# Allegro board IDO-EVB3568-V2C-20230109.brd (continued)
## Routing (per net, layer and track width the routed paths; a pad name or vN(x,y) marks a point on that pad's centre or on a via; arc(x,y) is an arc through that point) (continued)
SDMMC0_CMD: length 97.8
  TOP w0.127: J2.204 33.42,52.45 33.99,51.89 34.11,51.89 34.87,51.13 35.31,51.13 37.62,48.82 40.87,48.82 v1(41.1,48.59) ; R20.1 100.99,69.58 100.99,68.28 101.14,68.12 101.68,68.12 101.8,68 101.8,67.36 101.6,67.16 100.74,67.16 100.38,67.51 v1(100.38,68.86)
  BOTTOM w0.127: v1(41.1,48.59) 41.1,48.46 41.91,47.65 43.41,47.65 43.87,47.19 49.53,47.19 51.38,49.05 54.23,49.05 56.26,47.02 63.88,47.02 64.34,47.47 64.34,63.98 68.17,67.82 68.78,67.82 69.01,68.05 69.6,68.05 70.08,68.53 83.39,68.53 85.17,66.75 93.55,66.75 94.59,67.79 96.57,67.79 97.31,68.53 99.72,68.53 100.05,68.86 v1(100.38,68.86)
SDMMC0_CMD_: length 6.8
  TOP w0.127: J3.3 104,74.79 102.57,73.36 101.68,73.36 101.51,73.19 D3.6 D3.5 101.51,71.66 101.07,71.22 R20.2
SDMMC0_D0: length 97.1
  TOP w0.127: v1(42.67,49.61) 42.44,49.83 38.13,49.83 35.8,52.16 35.65,52.16 35.42,52.38 J2.196 ; R22.1 106.3,69.6 v1(105.49,69.6)
  BOTTOM w0.127: v1(42.67,49.61) 43.61,48.67 43.83,48.67 44.29,48.21 49.11,48.21 50.96,50.06 54.65,50.06 56.69,48.03 63.12,48.03 63.32,48.23 63.32,56.08 62.13,57.28 62.13,61.75 62.43,62.05 62.74,62.05 62.86,62.17 62.87,62.17 63.14,62.44 63.14,62.45 63.32,62.64 63.32,63.56 63.32,63.56 63.32,64.47 63.32,64.49 67.67,68.83 68.28,68.83 68.57,69.13 69.15,69.13 69.57,69.55 83.9,69.55 85.67,67.77 93.04,67.77 94.08,68.81 96.04,68.81 97.26,70.03 100.3,70.03 101.37,68.96 104.75,68.96 105.39,69.6 v1(105.49,69.6)
SDMMC0_D0_: length 6.9
  TOP w0.127: J3.7 108.41,75.56 108.41,74.5 108.1,74.19 106.83,74.19 106.51,73.87 D4.9 D4.2 106.51,71.59 106.76,71.35 106.76,70.91 R22.2
SDMMC0_D1: length 98.8
  TOP w0.127: v1(105.46,68.91) 105.87,68.91 105.99,69.04 106.72,69.04 R23.1 ; v1(42.04,49.35) 42.04,49.38 41.83,49.58 38,49.58 35.69,51.89 35.39,51.89 34.92,52.36 J2.198
  BOTTOM w0.127: v1(105.46,68.91) 105.11,68.91 104.9,68.71 101.24,68.71 100.18,69.77 97.38,69.77 96.16,68.55 94.21,68.55 93.17,67.51 85.55,67.51 83.77,69.29 69.7,69.29 69.27,68.86 68.68,68.86 68.4,68.58 67.81,68.58 63.58,64.34 63.58,63.67 63.58,62.36 63.02,61.8 62.76,61.8 62.41,61.44 62.41,57.38 63.58,56.21 63.58,47.96 63.4,47.78 56.58,47.78 54.55,49.81 51.07,49.81 49.21,47.96 44.19,47.96 43.73,48.41 43.43,48.41 42.75,49.1 42.29,49.1 v1(42.04,49.35)
SDMMC0_D1_: length 6.9
  TOP w0.127: J3.8 109.5,74.03 109.34,73.86 109.17,73.86 108.92,74.12 108.66,74.12 108.15,73.61 107.9,73.61 107.51,73.22 D4.7 D4.4 107.51,70.72 R23.2
SDMMC0_D2: length 98
  TOP w0.127: v1(42.49,48.59) 42.23,48.86 41.87,48.86 41.4,49.33 37.87,49.33 35.56,51.64 35.15,51.64 34.42,52.37 J2.200 ; v1(99.21,69.09) 99.21,69.55 R18.1
  BOTTOM w0.127: v1(42.49,48.59) 42.93,48.16 43.62,48.16 44.08,47.7 49.32,47.7 51.17,49.56 54.44,49.56 56.48,47.52 63.55,47.52 63.83,47.8 63.83,56.85 63.7,56.97 63.2,56.97 63.07,57.1 63.07,57.35 63.2,57.48 63.7,57.48 63.83,57.61 63.83,57.86 63.7,57.99 62.84,57.99 62.69,58.14 62.69,58.34 62.81,58.47 63.68,58.47 63.83,58.62 63.83,58.88 63.7,59 62.81,59 62.69,59.13 62.69,59.39 62.81,59.51 63.7,59.51 63.83,59.64 63.83,59.89 63.7,60.02 63.17,60.02 63.01,60.18 63.01,60.36 63.17,60.53 63.7,60.53 63.83,60.66 63.83,60.91 63.7,61.04 63.2,61.04 63.03,61.2 63.03,61.38 63.2,61.54 63.7,61.54 63.83,61.67 63.83,63.77 63.83,63.77 63.83,64.19 63.83,64.24 67.92,68.33 68.53,68.33 68.8,68.59 69.38,68.59 69.82,69.04 83.64,69.04 85.42,67.26 93.29,67.26 94.34,68.3 96.29,68.3 97.51,69.52 98.91,69.52 99.21,69.22 v1(99.21,69.09)
SDMMC0_D2_: length 6.8
  TOP w0.127: J3.1 101.8,74.78 101.27,74.24 100.41,74.24 100.01,73.85 D3.9 D3.2 100.01,71.66 99.54,71.2 99.19,71.2 99.11,71.11 R18.2
SDMMC0_D3: length 95.4
  TOP w0.127: J2.202 33.92,52.46 35,51.38 35.43,51.38 37.74,49.07 41.27,49.07 41.61,48.74 41.61,48.62 v1(41.83,48.39) ; R19.1 99.77,69.3 99.77,69.16 99.92,69.02 99.92,68.67 99.97,68.61 99.97,68.3 99.73,68.06 99.73,67.88 100,67.61 100,67.18 99.85,67.03 99.26,67.03 99.09,67.21 99.09,68.53 98.58,69.04 v1(98.48,69.04)
  BOTTOM w0.127: v1(41.83,48.39) 42.32,47.9 43.52,47.9 43.97,47.45 49.42,47.45 51.28,49.3 54.34,49.3 56.37,47.27 63.75,47.27 64.08,47.6 64.08,63.88 64.08,64.09 68.07,68.07 68.66,68.07 68.9,68.31 69.48,68.31 69.95,68.78 83.52,68.78 85.29,67.01 93.42,67.01 94.46,68.05 96.42,68.05 97.16,68.78 98.22,68.78 v1(98.48,69.04)
SDMMC0_D3_: length 6.8
  TOP w0.127: R19.2 100.13,71.11 100.34,71.32 100.74,71.32 101.01,71.59 D3.4 D3.7 101.01,73.32 101.55,73.86 102.21,73.86 102.9,74.56 J3.2
SDMMC0_DET_: length 6.9
  TOP w0.127: R24.2 108.01,70.62 D4.5 D4.6 108.01,73.09 108.15,73.23 109.3,73.23 110.6,74.54 J3.9
SDMMC0_DET_L: length 104.3
  TOP w0.127: R24.1 107.36,68.78 v1(107.26,68.78) ; v1(40.21,47.07) 39.7,47.07 38.96,47.8 37.11,47.8 35.51,49.4 34.26,49.4 33.81,49.86 32.56,49.86 32.36,50.06 32.36,52.3 32.42,52.36 J2.208
  BOTTOM w0.127: v1(40.21,47.07) 40.41,46.86 40.41,46.61 40.71,46.31 41.38,46.31 41.68,46.62 42.7,46.62 43.14,46.18 49.97,46.18 51.79,48.01 52.11,48.01 52.43,48.01 52.64,48.01 53.84,48.01 55.92,45.92 64.32,45.92 64.49,46.1 66.07,47.67 66.07,47.68 66.09,47.7 66.09,52.3 65.35,53.04 65.35,62.86 69.47,66.98 70.05,66.98 70.59,67.51 82.83,67.51 84.63,65.71 94.03,65.71 95.07,66.75 97.05,66.75 97.82,67.51 100.79,67.51 100.91,67.64 106.12,67.64 106.76,68.28 106.76,68.78 106.88,68.91 107.14,68.91 v1(107.26,68.78)
SDMMC2_CLK_M0: length 2.6
  TOP w0.127: J2.27 79.67,59.76 v1(79.45,59.54)
  BOTTOM w0.127: R187.1 79.45,59.07 v1(79.45,59.54)
SDMMC2_CMD_M0: length 57.2
  TOP w0.127: v1(95.83,45.09) 95.83,31.16 96.12,30.87 96.12,30.66 96.6,30.18 97.42,30.18 98.47,30.18 105.98,30.18 R185.2 107.7,27.5 R186.1 ; J2.25 80.2,61.43 80.2,60.34 80.24,60.3 v1(80.24,60.27)
  BOTTOM w0.127: v1(95.83,45.09) 95.83,45.11 95.15,45.8 94.01,45.8 93.9,45.69 93.48,45.69 85.63,45.69 82.25,49.08 82.25,52.65 82.37,52.78 82.5,52.78 82.63,52.91 82.63,53.16 82.5,53.29 82.37,53.29 82.25,53.42 82.25,57.73 82.12,57.86 81.86,57.86 80.24,59.49 v1(80.24,60.27)
SDMMC2_D0_M0: length 58.5
  TOP w0.127: R181.1 105.23,27.97 104.85,27.97 104.37,28.45 R180.2 103.64,29.13 96.4,29.13 96.21,29.13 95.11,30.24 95.11,30.45 94.69,30.87 94.69,43.56 94.54,43.71 94.03,44.23 94.03,46.74 v1(93.95,46.81) ; v1(82.3,60.15) 82.17,60.27 J2.17
  BOTTOM w0.127: v1(93.95,46.81) 93.57,47.19 85.67,47.19 83.26,49.61 83.26,51.89 84.4,53.04 84.4,56.08 84.28,56.21 83.39,56.21 83.26,56.34 83.26,56.59 83.39,56.72 84.28,56.72 84.4,56.85 84.4,57.1 84.28,57.23 83.39,57.23 83.26,57.35 83.26,57.61 83.39,57.73 84.28,57.73 84.4,57.86 84.4,58.12 84.28,58.24 83.39,58.24 83.26,58.37 83.26,58.62 83.39,58.75 83.39,59.06 v1(82.3,60.15)
SDMMC2_D1_M0: length 58.4
  TOP w0.127: R182.1 104.5,27.45 103.07,28.88 96.5,28.88 96.1,28.88 94.85,30.13 94.85,30.35 94.44,30.76 94.44,43.46 93.78,44.12 93.78,46.2 v1(93.27,46.71) ; v1(81.83,59.61) 81.83,60.31 81.67,60.47 J2.19
  BOTTOM w0.127: v1(93.27,46.71) 85.76,46.71 83.01,49.46 83.01,52.02 84.15,53.16 84.15,53.8 84.02,53.92 83.13,53.92 83.01,54.05 83.01,54.31 83.13,54.43 84.02,54.43 84.15,54.56 84.15,54.81 84.02,54.94 83.13,54.94 83.01,55.07 83.01,55.32 83.13,55.45 84.02,55.45 84.15,55.58 84.15,55.83 84.02,55.96 83.13,55.96 83.01,56.08 83.01,58.12 82.59,58.53 82.59,58.71 82.85,58.98 82.85,59.16 82.65,59.36 82.47,59.36 82.33,59.22 82.02,59.22 81.83,59.42 v1(81.83,59.61)
SDMMC2_D2_M0: length 59.2
  TOP w0.127: R183.1 109.6,28.98 107.9,30.68 96.81,30.68 96.63,30.87 96.63,31.08 96.37,31.35 96.37,43.84 96.85,44.33 96.85,45.44 v1(96.6,45.69) ; J2.21 81.17,60.3 v1(81.33,60.15)
  BOTTOM w0.127: v1(96.6,45.69) 95.76,46.53 94.33,46.53 94.15,46.35 93.84,46.35 93.69,46.2 85.88,46.2 82.75,49.33 82.75,52.15 83.13,52.53 83.13,53.54 82.75,53.92 82.75,57.99 81.33,59.42 v1(81.33,60.15)
SDMMC2_D3_M0: length 59.2
  TOP w0.127: R184.1 108.66,28.02 109.04,28.4 109.04,29.16 107.77,30.43 98.36,30.43 98.36,30.43 98.15,30.43 96.71,30.43 96.38,30.76 96.38,30.98 96.11,31.24 96.11,43.97 96.6,44.45 96.6,45.03 v1(95.86,45.77) ; J2.23 80.67,60.45 80.81,60.31 v1(80.81,59.66)
  BOTTOM w0.127: v1(80.81,59.66) 80.81,59.55 82.5,57.86 82.5,53.8 82.88,53.42 82.88,52.65 82.5,52.27 82.5,49.21 85.76,45.95 93.59,45.95 93.8,45.95 93.94,46.09 94.25,46.09 94.44,46.28 95.35,46.28 v1(95.86,45.77)
SPI0_CLK: length 6.6
  TOP w0.127: J24.3 129.87,53.67 129.87,51.77 128.6,50.5 128.19,50.5 127.81,50.88 R315.6
SPI0_CLK_M1: length 82.3
  TOP w0.127: R315.3 125.94,50.88 v1(125.93,50.88) ; v1(67.8,62.8) 67.73,62.74 66.57,62.74 66.17,62.34 J2.81
  BOTTOM w0.127: v1(125.93,50.88) 126.19,51.13 126.19,52.91 123.77,55.32 123.77,57.35 121.36,59.77 121.36,63.96 121.08,64.24 121.08,68.02 118.54,70.56 113.41,70.56 112.52,69.67 110.44,69.67 107.14,66.37 102.82,66.37 101.93,65.48 95.68,65.48 94.18,63.98 88.34,63.98 87.88,64.44 84,64.44 82.19,66.24 71.2,66.24 69.42,64.47 68.88,64.47 67.8,63.38 v1(67.8,62.8)
SPI0_CS0: length 10.1
  TOP w0.127: R315.5 127.45,50 127.97,49.48 129.11,49.48 130.63,51 131.78,51 132.16,51.38 132.16,53.42 J24.4
SPI0_CS0_M1: length 82.1
  TOP w0.127: R315.4 125.77,50.33 v1(125.3,49.86) ; J2.83 65.67,62.37 66.29,62.99 67.31,62.99 68,63.68 71.28,63.68 71.28,63.69 71.31,63.69 74.12,66.5 77.8,66.5 78.54,65.76 80.11,65.76 v1(80.37,65.51)
  BOTTOM w0.127: v1(80.37,65.51) 80.85,65.02 82.27,65.02 83.48,63.82 83.48,62.98 84,62.46 94.95,62.46 96.44,63.96 102.72,63.96 103.61,64.85 109.42,64.85 112.22,67.64 116.79,67.64 117.3,67.13 117.93,67.13 118.44,66.62 118.44,59.41 118.97,58.88 120.73,58.88 122.76,56.85 122.76,54.81 124.66,52.91 124.66,50.5 v1(125.3,49.86)
SPI0_MISO: length 10.1
  TOP w0.127: J24.2 133.55,57.23 132.54,56.21 130.51,56.21 129.31,55.02 129.31,52.6 128.22,51.51 127.83,51.51 127.7,51.38 R315.7
SPI0_MISO_M1: length 82.7
  TOP w0.127: J2.87 64.67,62.29 65.89,63.5 67.1,63.5 67.79,64.19 71.05,64.19 71.53,64.66 73.87,67.01 78.05,67.01 78.79,66.27 85.34,66.27 87.45,64.16 v1(87.45,63.7) ; R315.2 125.48,51.38 125.2,51.66 v1(125.2,51.69)
  BOTTOM w0.127: v1(125.2,51.69) 125.68,52.17 125.68,52.65 123.27,55.07 123.27,57.1 120.8,59.56 119.41,59.56 118.95,60.02 118.95,67.39 117.93,68.4 112.85,68.4 112.22,69.04 110.57,69.04 107.39,65.86 103.07,65.86 102.18,64.97 95.94,64.97 94.44,63.47 87.68,63.47 v1(87.45,63.7)
SPI0_MOSI: length 7.5
  TOP w0.127: J24.1 131.01,57.1 129.06,55.14 129.06,52.73 128.09,51.77 127.84,51.77 127.67,51.93 R315.8
SPI0_MOSI_M1: length 80.3
  TOP w0.127: J2.85 65.17,62.3 66.12,63.25 67.2,63.25 67.89,63.93 71.17,63.93 73.99,66.75 77.93,66.75 78.66,66.01 80.54,66.01 v1(81.05,65.51) ; v1(125.2,52.4) 125.67,51.93 R315.1
  BOTTOM w0.127: v1(125.2,52.4) 125.2,52.76 123.01,54.94 123.01,56.97 120.78,59.21 119.35,59.21 118.69,59.87 118.69,66.75 118.02,67.42 117.39,67.42 116.92,67.89 112.11,67.89 109.32,65.1 103.48,65.1 102.59,64.21 96.32,64.21 94.82,62.71 84.23,62.71 83.74,63.2 83.74,63.93 82.4,65.28 81.28,65.28 v1(81.05,65.51)
SPK_CTL_H_GPIO3_B0: length 12.4
  TOP w0.127: R89.1 81.1,63.58 v1(81.1,63.02) ; J2.53 73.17,60.35 v1(72.97,60.15)
  BOTTOM w0.127: v1(72.97,60.15) 72.97,60.66 75.34,63.02 75.64,63.02 75.84,63.22 78.89,63.22 79.15,63.47 80.98,63.47 81.1,63.35 v1(81.1,63.02)
SPK_MUTE_H_GPIO3_A7: length 13.2
  TOP w0.127: R90.1 83.2,63.2 v1(82.17,63.2) ; v1(74.14,62.99) 73.71,62.56 72.97,62.56 72.67,62.26 J2.55
  BOTTOM w0.127: v1(74.14,62.99) 74.17,62.99 74.73,63.55 75.41,63.55 75.59,63.73 78.64,63.73 78.89,63.98 81.33,63.98 82.12,63.2 v1(82.17,63.2)
SYS_LED_GPIO4_C5: length 56.3
  TOP w0.127: R8.1 76.53,76.66 76.78,76.4 76.78,73.28 76.66,73.15 75.93,73.15 75.72,73.15 75.18,72.62 75.18,71.41 75.46,71.13 75.46,70.18 v1(75.51,70.13) ; v1(51.49,51.13) 51.49,51.19 51.51,51.21 51.51,51.77 50.92,52.35 J2.142
  BOTTOM w0.127: v1(75.51,70.13) 75.46,70.18 74.68,70.18 73.96,70.89 72.62,70.89 71.86,70.13 70.79,70.13 70.41,70.51 70,70.51 68.88,69.39 68.45,69.39 68.15,69.09 67.49,69.09 61.44,63.04 61.44,57.2 62.79,55.85 62.79,49.12 61.95,48.29 56.79,48.29 54.76,50.32 52.07,50.32 51.51,50.88 51.51,51.05 51.49,51.07 v1(51.49,51.13)
SYS_RESETN: length 183.9
  TOP w0.127: R311.4 127.22,28.03 126.75,28.5 126.75,28.76 125.05,30.45 124.95,30.45 124.72,30.68 124.51,30.68 124.51,30.68 124.36,30.68 124.1,30.94 v1(123.77,30.94) ; v1(24.36,55.88) 24.43,55.96 24.97,55.96 26.37,57.35 26.37,59.94 25.67,60.64 J2.235
  BOTTOM w0.127: v1(24.36,55.88) 25.3,55.88 25.65,55.52 25.65,53.39 24.56,52.3 24.56,44.46 23.58,43.48 23.58,42.86 23.46,42.74 23.46,28.81 25.98,26.28 25.98,23.95 24.97,22.94 24.97,22.17 24.08,21.29 24.08,19.51 24.59,19 27.23,19 28.24,17.98 28.24,14.63 29.18,13.69 29.18,13.24 29.68,12.75 29.68,11.92 30.3,11.29 30.3,8.74 31.22,7.82 35.26,7.82 37.69,5.38 70.66,5.38 77.8,12.52 77.8,15.06 78.18,15.44 78.18,17.09 80.85,19.76 81.23,19.76 81.87,20.4 81.87,20.68 84.04,22.85 84.04,22.87 84.98,23.81 85,23.81 86.11,24.92 89.05,24.92 89.41,24.56 91.64,24.56 93.27,26.19 93.27,28.73 94.03,29.49 109.27,29.49 109.75,29.01 111.58,29.01 112.27,28.32 113.97,28.32 115.82,30.18 115.85,30.18 121.41,35.74 122.38,35.74 122.5,35.61 122.5,32.21 v1(123.77,30.94)
TP0_INT: length 49.2
  TOP w0.127: v1(31.83,10.64) 31.83,10.29 31.55,10.01 31.19,10.01 28.5,7.31 v1(28.5,6.78)
  BOTTOM w0.127: J15.5 18.08,27.51 17.6,27.03 17.6,20.14 19.51,18.24 20.65,18.24 22.3,16.59 22.3,13.67 24.33,11.63 25.6,11.63 27.51,9.73 27.51,7.06 27.79,6.78 v1(28.5,6.78) ; v1(31.83,10.64) 31.11,11.35 31.11,12.58 31.09,12.6 31.09,12.62 30.68,13.03 30.68,14.3 29.54,15.44 29.54,16.59 29.06,17.07 29.06,17.88 29.29,18.11 J31.3 29.29,20.02 29.67,20.4 31.55,20.4 31.71,20.56 D48.4 D48.7 31.71,22.95 R114.2
TP0_INT_L_GPIO3_A3: length 93.1
  TOP w0.127: v1(42.88,19.84) 42.01,20.7 39.63,20.7 39.45,20.88 v1(38.79,20.88) ; J2.63 70.67,62.25 70.21,62.71 70.2,62.71 v1(70.18,62.73)
  BOTTOM w0.127: v1(70.18,62.73) 70.18,62.64 68.58,61.04 67.89,61.04 67.64,60.78 67.64,46.94 65.1,44.4 55.22,44.4 53.14,46.48 52.43,46.48 52.02,46.08 52.02,45.24 48.59,41.81 48.59,37.29 49.23,36.65 49.23,27.51 50.24,26.49 50.24,22.68 49.15,21.59 47.09,21.59 45.82,20.32 45.82,19.96 45.26,19.41 43.28,19.41 42.93,19.76 42.93,19.79 v1(42.88,19.84) ; R114.1 31.88,26.54 32.18,26.85 32.58,26.85 32.79,26.85 34.26,28.31 37.8,28.31 38.22,28.31 38.77,27.76 38.77,26.38 38.51,26.12 38.51,21.16 v1(38.79,20.88)
TP0_RST: length 46.4
  TOP w0.127: v1(27.98,7.25) 28.08,7.25 31.17,10.34 v1(31.17,10.49)
  BOTTOM w0.127: J15.4 18.12,27.01 17.86,26.75 17.86,20.27 19.63,18.49 20.78,18.49 22.56,16.71 22.56,13.79 24.46,11.89 25.73,11.89 27.76,9.86 27.76,7.47 v1(27.98,7.25) ; R113.2 31.21,22.83 D48.6 D48.5 31.21,20.79 31.06,20.65 29.41,20.65 28.79,20.03 J31.2 28.79,16.96 29.29,16.46 29.29,15.32 30.43,14.17 30.43,12.9 30.86,12.47 30.86,11.23 31.17,10.92 v1(31.17,10.49)
TP0_RST_L_GPIO3_A4: length 94.8
  TOP w0.127: J2.61 71.17,62.46 70.41,63.22 69.7,63.22 v1(69.68,63.2)
  BOTTOM w0.127: R113.1 31.45,24.55 31.45,26.49 32.05,27.1 32.69,27.1 34.15,28.57 37.69,28.57 38.32,28.57 38.62,28.27 38.62,28.27 39.02,27.87 39.02,26.28 38.79,26.04 38.79,21.56 39.75,20.6 42.77,20.6 43.71,19.66 45.03,19.66 45.57,20.19 45.57,20.45 46.96,21.84 49.04,21.84 49.99,22.79 49.99,26.37 48.84,27.51 48.84,36.65 48.34,37.16 48.34,41.92 51.77,45.35 51.77,46.18 52.32,46.74 53.29,46.74 55.37,44.65 64.97,44.65 67.39,47.07 67.39,60.91 67.77,61.29 68.47,61.29 69.67,62.49 69.67,63.19 v1(69.68,63.2)
TP0_SCL: length 54.1
  TOP w0.127: v1(31.37,9.5) 31.05,9.5 29.03,7.49 29.03,7.47 28.98,7.42 28.98,6.55 28.73,6.3 v1(28.02,6.3)
  BOTTOM w0.127: R115.2 32.71,22.99 D48.9 D48.2 32.71,20.52 32.33,20.14 30.05,20.14 29.79,19.88 J31.4 29.79,18.11 30.02,17.88 30.02,15.34 30.94,14.43 30.94,13.16 32.33,11.76 32.33,9.88 31.95,9.5 v1(31.37,9.5) ; J15.6 17.08,28.01 16.59,27.51 16.59,25.25 17.35,24.49 17.35,20.02 18.49,18.87 18.49,14.17 20.02,12.65 22.94,12.65 24.21,11.38 25.48,11.38 27.25,9.6 27.25,6.81 27.76,6.3 v1(28.02,6.3)
TP0_SDA: length 56.1
  TOP w0.127: v1(29.16,6.05) 29.29,6.17 29.29,7.38 30.73,8.82 v1(31.34,8.82)
  BOTTOM w0.127: J15.7 17.22,28.51 16.33,27.62 16.33,25.1 17.09,24.33 17.09,19.89 18.24,18.75 18.24,14.07 19.91,12.4 22.81,12.4 24.08,11.13 25.35,11.13 27,9.47 27,6.43 27.64,5.79 28.91,5.79 v1(29.16,6.05) ; R116.2 33.66,23.12 33.21,22.67 D48.10 D48.1 33.21,20.53 32.56,19.89 30.57,19.89 30.29,19.61 J31.5 30.29,15.46 31.19,14.55 31.19,13.28 32.61,11.86 32.61,9.7 31.73,8.82 v1(31.34,8.82)
TP1_INT: length 5.8
  TOP w0.127: R95.2 92.91,13.46 D34.2 D34.9 92.91,10.86 92.66,10.62 92.15,10.62 91.04,9.5 J13.5
TP1_INT_L_GPIO3_C0: length 56.6
  TOP w0.127: J2.68 69.42,52.27 76.66,45.03 76.66,43.64 80.47,39.83 80.47,35 80.59,34.87 80.59,28.78 78.87,27.05 78.87,25.35 v1(79.98,24.23) ; R95.1 92.91,14.68 93.22,14.99 93.22,16.28 90.97,18.52 82.28,18.52 79.07,21.74 79.07,22.96 v1(78.84,23.19)
  BOTTOM w0.127: v1(79.98,24.23) 79.6,24.23 78.84,23.47 v1(78.84,23.19)
TP1_RST: length 5.9
  TOP w0.127: J13.4 91.54,9.5 92.41,10.36 92.91,10.36 93.41,10.86 D34.10 D34.1 93.41,12.56 93.65,12.81 93.65,13.31 R94.2
TP1_RST_L_GPIO3_C1: length 56.7
  TOP w0.127: v1(79.55,23.32) 79.32,23.09 79.32,21.84 82.39,18.78 91.08,18.78 91.09,18.77 91.11,18.77 93.55,16.33 93.55,14.94 93.8,14.68 R94.1 ; J2.66 69.92,52.15 76.91,45.16 76.91,43.76 80.72,39.95 80.72,35.13 80.85,35 80.85,28.65 79.12,26.92 79.12,25.6 80.01,24.71 80.47,24.71 v1(80.59,24.59)
  BOTTOM w0.127: v1(79.55,23.32) 79.76,23.32 80.59,24.16 v1(80.59,24.59)
TP1_SCL: length 5.3
  TOP w0.127: J13.6 90.54,9.51 91.9,10.87 91.9,11.19 D34.7 D34.4 91.91,13.35 R96.2
TP1_SDA: length 5.4
  TOP w0.127: J13.7 90.04,9.52 91.41,10.89 D34.6 D34.5 91.41,13.2 R97.2
TYPEC_CC1: length 43
  TOP w0.127: v1(115.7,67.16) 115.9,67.36 115.9,72.85 v1(116.13,73.08) ; J5.A5 129.22,82.2 D8.2 128.6,81.58 128.6,81.08 128.47,80.95 128.47,80.34 128.16,80.03 127.55,80.03 125.32,77.8 125.32,75.97 v1(124.38,75.03)
  BOTTOM w0.127: v1(115.7,67.16) 116.89,67.16 117.17,66.88 117.81,66.88 118.19,66.5 118.19,59.21 118.95,58.45 118.95,57.41 R38.1 118.19,56.65 D11.C ; v1(124.38,75.03) 124,75.03 123.65,75.39 115.95,75.39 115.29,74.73 115.29,73.91 v1(116.13,73.08)
TYPEC_CC2: length 37.9
  TOP w0.127: J5.B5 126.22,83.41 125.83,83.03 125.83,82.65 125.81,82.63 125.81,82.53 125.37,82.09 D9.2 124.97,82.09 124.84,81.96 124.84,81.05 124.39,80.59 123.95,80.59 122.71,79.35 122.71,76.33 123.39,75.64 123.39,73.74 122.94,73.28 121.06,73.28 120.73,73.61 117.81,73.61 117.64,73.44 117.64,72.22 117.14,71.73 117.14,67.54 117.32,67.36 117.32,66.62 v1(117.56,66.38)
  BOTTOM w0.127: v1(117.56,66.38) 117.93,66.01 117.93,60.22 115.9,58.19 115.9,57.39 R40.1 116.41,56.88 D13.C
UART0_CTSN: length 110.4
  TOP w0.127: J2.134 52.92,50.93 51.41,49.42 51.41,46.37 51.3,46.26 51.3,43.78 51.84,43.24 51.84,40.84 51.03,40.02 51.03,39.7 51.05,39.68 v1(51.05,39.67) ; R310.2 126.06,39.82 125.43,40.46 125.43,40.97 v1(124.79,41.61)
  BOTTOM w0.127: v1(124.79,41.61) 124.16,41.61 124,41.45 122.02,41.45 121.11,42.37 120.6,42.37 119.84,41.61 117.81,41.61 117.3,42.11 113.61,42.11 109.3,37.8 106.38,37.8 105.61,37.03 100.15,37.03 99.77,36.65 97.32,36.65 94.53,39.45 77.93,39.45 75.77,37.29 74.75,37.29 74.24,36.78 74.24,35.76 67.13,28.65 56.85,28.65 56.08,29.41 52.78,29.41 51.26,30.94 51.26,39.47 51.05,39.67 v1(51.05,39.67)
UART0_CTSN_: length 7
  TOP w0.127: J24.16 132.41,38.43 130.51,38.43 129.11,39.82 R310.7
UART0_RTSN: length 109.6
  TOP w0.127: J2.128 54.42,51.71 51.92,49.21 51.92,46.16 51.81,46.05 51.81,43.99 52.55,43.25 52.55,42.86 v1(52.56,42.85) ; R310.1 126.15,40.37 125.81,40.72 v1(125.81,41.38)
  BOTTOM w0.127: v1(125.81,41.38) 125.3,41.88 125.3,42.24 124.92,42.62 124.18,42.62 123.52,41.96 122.28,41.96 121.36,42.88 113.23,42.88 108.92,38.56 105.99,38.56 105.23,37.8 99.77,37.8 99.39,37.41 97.7,37.41 95.05,40.06 94.9,40.21 77.55,40.21 75.39,38.05 74.37,38.05 73.48,37.16 73.48,36.14 66.75,29.41 57.23,29.41 56.46,30.18 53.16,30.18 52.02,31.32 52.02,41.49 52.56,42.03 v1(52.56,42.85)
UART0_RTSN_: length 3.8
  TOP w0.127: R310.8 130.21,40.37 J24.15
UART0_RX: length 110.8
  TOP w0.127: v1(124.33,42.11) 124.97,42.75 125.93,42.75 126.18,42.5 R309.3 ; v1(52.78,44.53) 52.78,44.88 53.35,45.45 53.35,45.94 52.93,46.35 52.93,48.79 56.42,52.28 J2.120
  BOTTOM w0.127: v1(52.78,44.53) 52.22,44.53 51.51,43.81 51.51,31.06 52.91,29.67 56.21,29.67 56.97,28.91 67.01,28.91 73.99,35.89 73.99,36.91 74.63,37.54 75.64,37.54 77.8,39.7 94.69,39.7 97.49,36.91 99.64,36.91 100.03,37.29 105.49,37.29 106.25,38.05 109.17,38.05 113.49,42.37 117.42,42.37 117.93,41.86 119.71,41.86 120.47,42.62 121.23,42.62 122.15,41.71 123.72,41.71 124.13,42.11 v1(124.33,42.11)
UART0_RX_: length 6.7
  TOP w0.127: R309.6 129.75,42.5 130.4,43.15 132.51,43.15 J24.14
UART0_TX: length 108.2
  TOP w0.127: v1(52.78,45.54) 52.68,45.64 52.68,48.89 55.92,52.13 J2.122 ; v1(125.81,42.11) 125.97,41.95 R309.4
  BOTTOM w0.127: v1(125.81,42.11) 124.79,43.13 123.67,43.13 123.55,43.01 121.97,43.01 121.81,43.17 121.6,43.38 113,43.38 112.85,43.23 108.68,39.07 105.74,39.07 104.98,38.3 99.52,38.3 98.88,38.94 96.89,38.94 95.56,40.27 95.11,40.72 77.29,40.72 75.13,38.56 74.12,38.56 72.97,37.41 72.97,36.47 66.42,29.92 57.48,29.92 56.72,30.68 53.42,30.68 52.53,31.57 52.53,41.27 54.18,42.93 54.18,44.7 53.59,45.29 53.04,45.29 v1(52.78,45.54)
UART0_TX_: length 3.5
  TOP w0.127: R309.5 129.71,41.95 129.87,42.11 J24.13
UART2_RX_M0: length 12.8
  TOP w0.127: v1(56.59,63.32) 56.59,63.53 55.7,64.41 R25.1 ; J2.116 57.42,54.12 57.61,54.31 57.61,57.73 56.36,58.98 56.36,59.99 v1(56.26,60.1)
  BOTTOM w0.127: v1(56.26,60.1) 56.26,60.12 56.08,60.3 56.08,62.38 56.21,62.51 56.21,62.94 v1(56.59,63.32)
UART2_TX_M0: length 15.8
  TOP w0.127: v1(55.74,62.76) 52.58,62.76 52.15,63.2 R26.1 ; v1(55.75,59.61) 55.75,59.21 57.35,57.61 57.35,54.56 56.92,54.13 J2.118
  BOTTOM w0.127: v1(55.75,59.61) 55.58,59.79 55.58,62.6 v1(55.74,62.76)
UART4_RX: length 6.7
  TOP w0.127: R309.7 128.22,43 128.22,43 129.62,43 130.12,43.51 132.41,43.51 J24.12
UART4_RX_M1: length 70.9
  TOP w0.127: v1(125.68,43.51) 126.19,43 R309.2 ; J2.82 65.92,51.7 67.26,50.37 68.68,50.37 74.37,44.68 74.37,44.02 v1(74.88,43.51)
  BOTTOM w0.127: v1(74.88,43.51) 75.11,43.74 79.22,43.74 81.99,40.97 95.22,40.97 95.96,40.23 97,39.19 99.01,39.19 99.64,38.56 101.84,38.56 104.85,38.56 105.61,39.32 108.58,39.32 112.75,43.49 112.9,43.64 121.7,43.64 122.07,43.26 123.44,43.26 123.56,43.38 124.9,43.38 124.97,43.31 125.48,43.31 v1(125.68,43.51)
UART4_TX: length 4
  TOP w0.127: R309.8 127.93,43.55 128.09,43.38 129.49,43.38 130.76,44.65 J24.11
UART4_TX_M1: length 70.1
  TOP w0.127: v1(125.68,44.2) 126.33,43.55 R309.1 ; J2.80 66.42,51.59 67.39,50.62 68.79,50.62 74.63,44.78 74.63,44.5 v1(74.88,44.25)
  BOTTOM w0.127: v1(74.88,44.25) 75.13,43.99 79.35,43.99 82.12,41.22 95.33,41.22 97.1,39.45 99.14,39.45 99.77,38.81 101.94,38.81 101.94,38.81 104.72,38.81 105.49,39.57 108.47,39.57 112.49,43.59 112.79,43.89 121.6,43.89 121.6,43.89 121.81,43.89 122.18,43.52 123.34,43.52 123.46,43.64 125.12,43.64 v1(125.68,44.2)
UART5_RX: length 6.7
  TOP w0.127: R316.6 127.77,48.02 127.88,47.92 128.06,47.92 128.42,48.29 132.46,48.29 J24.10
UART5_RX_M1: length 67.4
  TOP w0.127: v1(76.3,47.41) 75.45,47.41 70.92,51.94 J2.62 ; R316.3 126,48.02 v1(125.68,47.7)
  BOTTOM w0.127: v1(125.68,47.7) 125.3,47.32 125.3,44.91 124.54,44.15 123.25,44.15 123.16,44.06 122.35,44.06 122.02,44.4 121.39,44.4 121.38,44.4 112.53,44.4 112.38,44.25 108.21,40.08 105.23,40.08 104.47,39.32 102.16,39.32 102.16,39.32 100.03,39.32 99.39,39.95 97.36,39.95 95.58,41.73 82.37,41.73 76.7,47.41 v1(76.3,47.41)
UART5_TX: length 4.1
  TOP w0.127: J24.9 130.18,48.03 128.55,48.03 128.17,47.65 127.91,47.65 127.74,47.47 R316.5
UART5_TX_M1: length 67.6
  TOP w0.127: v1(75.9,46.86) 75.62,46.86 70.42,52.06 J2.64 ; v1(125.81,46.79) 125.81,47.07 126.21,47.47 R316.4
  BOTTOM w0.127: v1(75.9,46.86) 76.86,46.86 82.25,41.48 95.45,41.48 97.23,39.7 99.26,39.7 99.9,39.07 102.05,39.07 104.6,39.07 105.36,39.83 108.32,39.83 112.64,44.15 121.49,44.15 121.91,44.15 122.28,43.77 123.23,43.77 123.35,43.89 124.66,43.89 125.55,44.78 125.55,46.53 v1(125.81,46.79)
UART7_RX: length 3.9
  TOP w0.127: R316.8 127.61,49.07 127.79,48.9 130.18,48.9 J24.7
UART7_RX_M1: length 67
  TOP w0.127: J2.58 71.92,51.7 75.23,48.39 v1(76.28,48.39) ; v1(125.04,48.51) 125.6,49.07 R316.1
  BOTTOM w0.127: v1(125.04,48.51) 124.79,48.26 124.79,45.16 124.28,44.65 123.04,44.65 122.95,44.57 122.57,44.57 122.23,44.91 121.17,44.91 121.17,44.91 112.32,44.91 111.88,44.46 108,40.59 104.98,40.59 104.22,39.83 102.37,39.83 102.37,39.83 100.28,39.83 99.64,40.46 97.61,40.46 95.83,42.24 82.63,42.24 76.48,48.39 v1(76.28,48.39)
UART7_TX: length 6.6
  TOP w0.127: R316.7 127.77,48.52 127.89,48.64 132.46,48.64 J24.8
UART7_TX_M1: length 67.2
  TOP w0.127: J2.60 71.42,52.43 71.58,52.27 71.58,51.66 75.39,47.85 75.74,47.85 v1(75.77,47.88) ; R316.2 v1(125.81,48.52)
  BOTTOM w0.127: v1(75.77,47.88) 76.61,47.88 82.5,41.99 95.71,41.99 97.49,40.21 99.52,40.21 100.15,39.57 102.26,39.57 104.34,39.57 105.11,40.34 108.11,40.34 112.28,44.5 112.43,44.65 121.28,44.65 122.12,44.65 122.46,44.31 123.06,44.31 123.14,44.4 124.41,44.4 125.04,45.03 125.04,47.76 v1(125.81,48.52)
UART8_CTSN_M0: length 146.5
  TOP w0.127: v1(99.67,7.8) 100.18,7.8 100.33,7.65 101.3,7.65 v1(101.35,7.7) ; U18.41 108.56,11.54 108.59,11.51 R201.1 108.47,10.74 108.03,10.74 v1(107.39,10.11) ; J2.233 26.17,60.64 26.62,60.2 26.62,57.15 25.16,55.69 24.9,55.69 24.46,55.24 24.43,55.24 v1(24.39,55.2)
  BOTTOM w0.127: v1(24.39,55.2) 24.34,55.2 24.24,55.11 24.24,53.12 23.8,52.68 23.8,44.77 22.82,43.8 22.82,43.27 22.7,43.15 22.7,28.49 25.17,26.02 25.17,24.28 24.21,23.32 24.21,22.58 23.29,21.67 23.29,18.9 24.31,17.88 24.31,14.71 25.22,13.79 28.01,13.79 28.42,13.37 28.42,12.93 28.91,12.44 28.91,12.02 28.91,11.6 29.54,10.98 29.54,8.37 30.85,7.06 34.87,7.06 37.31,4.62 71.04,4.62 72.09,5.66 90.58,5.66 90.86,5.94 97.04,5.94 97.94,6.84 98.69,7.59 99.47,7.59 v1(99.67,7.8) ; v1(101.35,7.7) 101.6,7.7 102.11,8.2 102.44,8.2 103.71,9.47 106.76,9.47 v1(107.39,10.11)
UART8_RTSN_M0: length 148.8
  TOP w0.127: v1(99.36,8.43) 99.39,8.46 v1(101.37,8.46) ; v1(25.1,55.22) 25.17,55.22 27,57.05 27,60.33 26.67,60.65 J2.231 ; v1(110.95,10.49) 110.95,11.63 111.26,11.94 U18.44
  BOTTOM w0.127: v1(25.1,55.22) 25.1,55.22 24.6,54.73 24.6,53.1 24.05,52.55 24.05,44.67 23.08,43.69 23.08,43.14 22.95,43.02 22.95,28.59 25.45,26.1 25.45,24.18 24.46,23.19 24.46,22.43 23.55,21.51 23.55,19.08 24.56,18.07 24.56,14.83 25.35,14.05 28.11,14.05 28.68,13.48 28.68,13.03 29.17,12.54 29.17,11.92 29.17,11.71 29.79,11.08 29.79,8.48 30.96,7.32 35,7.32 37.44,4.88 70.92,4.88 71.96,5.92 90.42,5.92 90.7,6.2 96.94,6.2 97.69,6.95 98.59,7.85 99.06,7.85 99.36,8.15 v1(99.36,8.43) ; v1(101.37,8.46) 102.31,8.46 103.58,9.73 105.87,9.73 106.88,10.74 110.69,10.74 v1(110.95,10.49)
UART8_RX_M0: length 145
  TOP w0.127: v1(21.29,45.39) 20.94,45.73 20.94,48.86 21.23,49.15 22.37,49.15 22.38,49.16 22.4,49.16 24.92,51.69 J2.238 ; U18.42 109.46,12.49 110.06,11.89 110.06,10.49 109.8,10.24 109.4,10.24 v1(109.04,9.88)
  BOTTOM w0.127: v1(21.29,45.39) 21.03,45.39 20.49,44.85 20.49,43.54 21.16,42.88 21.16,41.71 21.16,41.71 21.16,26.62 20.14,25.6 20.02,25.6 19.25,24.84 19.25,22.17 18.49,21.41 18.49,20.02 19.76,18.75 20.9,18.75 22.81,16.84 22.81,13.92 24.59,12.14 25.86,12.14 28.14,9.86 28.14,7.84 30.32,5.66 34.37,5.66 37.16,2.87 71.32,2.87 72.85,4.39 91.47,4.39 91.73,4.66 97.2,4.66 97.21,4.67 97.57,4.67 99.21,6.32 100.45,6.32 100.97,6.83 101.88,6.83 104.01,8.97 107.65,8.97 108.56,9.88 v1(109.04,9.88)
UART8_TX_M0: length 142.2
  TOP w0.127: J2.236 25.42,51.83 22.5,48.91 22.49,48.91 22.48,48.9 21.41,48.9 21.2,48.68 21.2,46.14 21.77,45.57 21.77,44.48 21.67,44.38 21.67,43.94 v1(21.59,43.87) ; v1(110.36,10.11) U18.43
  BOTTOM w0.127: v1(21.59,43.87) 21.59,43.74 21.67,43.66 21.67,42.94 21.67,42.94 21.67,25.98 22.78,24.87 22.78,22.81 21.79,21.82 21.79,18.36 23.06,17.09 23.06,14.1 24.77,12.4 25.98,12.4 28.4,9.98 28.4,7.95 30.43,5.92 34.49,5.92 37.29,3.12 71.22,3.12 72.74,4.65 91.32,4.65 91.58,4.91 97.09,4.91 97.1,4.93 97.46,4.93 99.11,6.57 100.34,6.57 100.86,7.09 101.7,7.09 103.84,9.22 107.52,9.22 108.66,10.36 110.1,10.36 v1(110.36,10.11)
USB1_PWREN_H_GPIO3_A5: length 95.6
  TOP w0.127: R57.1 122.94,23.13 119.71,26.37 119.71,30.94 118.49,32.16 118.49,36.2 119.33,37.03 119.33,40.59 111.2,48.72 v1(110.82,48.72) ; v1(72.29,60.15) 72.09,60.15 71.67,60.56 J2.59
  BOTTOM w0.127: v1(110.82,48.72) 110.85,48.74 110.85,49.71 110.39,50.16 103.85,50.16 102.05,48.36 99.04,48.36 98.58,48.36 97.84,47.62 95.87,47.62 95.03,48.46 94.61,48.46 94.61,48.46 90.25,48.46 87.33,51.38 87.33,52.91 88.44,54.03 88.44,55.7 92.05,59.31 92.05,60.93 91.54,61.44 83.08,61.44 81.66,62.86 81.66,63.27 81.2,63.73 79.02,63.73 78.77,63.47 75.72,63.47 75.53,63.29 75.23,63.29 72.29,60.35 v1(72.29,60.15)
USB2_HOST2_DM: length 34.2
  TOP w0.114: v1(79.32,54.56) 79.54,54.35 79.54,54.14 79.42,54.02 J2.28 ; v1(91.57,60.27) 91.35,60.49 91.35,61.2 90.86,61.7 89.9,61.7 88.21,63.38 88.21,64.49 85.7,67.01 85.7,68.55 85.95,68.8 L6.2 85.95,69.27 R42.1
  BOTTOM w0.114: v1(91.57,60.27) 91.23,60.61 91.23,60.64 90.97,60.9 82.77,60.9 82.25,61.42 79.3,61.42 78.32,60.44 78.32,57.09 79.51,55.89 79.51,54.76 v1(79.32,54.56)
USB2_HOST2_DM_: length 13
  TOP w0.114: R42.2 85.95,70.33 L6.3 85.95,70.8 85.66,71.08 85.66,71.49 85.51,71.64 85.51,71.8 85.63,71.92 D14.5 D14.6 85.63,73.3 85.5,73.43 85.5,73.66 85.88,74.05 85.88,74.31 v2(86.14,74.57)
  BOTTOM w0.114: J6.2 86.67,80.47 86.56,80.35 86.56,80.16 85.57,79.17 85.57,78.61 86.46,77.72 86.46,76.86 85.55,75.95 85.55,75.41 85.88,75.08 85.88,74.84 v2(86.14,74.57)
USB2_HOST2_DP: length 34.3
  TOP w0.114: v1(90.88,60.27) 91.11,60.5 91.11,61.1 90.76,61.46 89.8,61.46 87.97,63.28 87.97,64.39 85.46,66.91 85.46,68.54 85.15,68.85 L6.1 85.15,69.27 R43.1 ; v1(80,54.56) 79.78,54.34 79.78,54.16 79.92,54.01 J2.26
  BOTTOM w0.114: v1(90.88,60.27) 90.99,60.38 90.99,60.54 90.87,60.66 90.37,60.66 90.25,60.53 89.99,60.53 89.87,60.66 89.61,60.66 89.48,60.53 89.23,60.53 89.1,60.66 88.85,60.66 88.72,60.53 88.47,60.53 88.34,60.66 88.09,60.66 87.96,60.53 87.71,60.53 87.58,60.66 87.33,60.66 87.2,60.53 86.94,60.53 86.82,60.66 86.56,60.66 86.44,60.53 86.18,60.53 86.06,60.66 85.8,60.66 85.67,60.53 85.42,60.53 85.29,60.66 85.04,60.66 84.91,60.53 84.66,60.53 84.53,60.66 82.67,60.66 82.15,61.18 79.4,61.18 78.56,60.34 78.56,57.19 79.76,55.99 79.76,54.81 v1(80,54.56)
USB2_HOST2_DP_: length 13
  TOP w0.114: R43.2 85.15,70.33 L6.4 85.15,70.8 85.42,71.07 85.42,71.39 85.27,71.54 85.27,71.78 85.13,71.92 D14.4 D14.7 85.13,73.3 85.26,73.42 85.26,73.76 85.64,74.15 85.64,74.31 v2(85.38,74.57)
  BOTTOM w0.114: v2(85.38,74.57) 85.64,74.82 85.64,74.98 85.31,75.31 85.31,76.05 86.22,76.96 86.22,77.62 85.33,78.51 85.33,79.27 86.32,80.26 86.32,80.35 86.2,80.47 J6.3
USB2_HOST2_PWREN_H_GPIO0_A6: length 53.5
  TOP w0.127: v1(94.62,69.32) 94.41,69.32 U5.4 ; v1(61.54,54.56) 59.18,54.56 58.92,54.31 J2.110
  BOTTOM w0.127: v1(94.62,69.32) 94.36,69.06 93.95,69.06 92.91,68.02 85.83,68.02 84.05,69.8 76.56,69.8 75.74,70.61 74.63,70.61 74.09,71.15 72.49,71.15 71.73,70.38 70.92,70.38 70.54,70.76 69.88,70.76 68.76,69.65 68.33,69.65 68.02,69.34 67.36,69.34 61.59,63.58 60.78,63.58 60.45,63.25 60.45,57.43 61.54,56.34 v1(61.54,54.56)
USB2_HOST3_DM: length 37.4
  TOP w0.114: R71.2 106.45,47.45 106.45,47.6 v1(106.73,47.88) ; v1(80,47.93) 80.34,48.27 80.34,48.73 80.25,48.82 80.25,51.94 80.55,52.25 80.55,52.36 80.42,52.5 J2.24
  BOTTOM w0.114: v1(80,47.93) 80.3,47.63 80.3,47.02 83.54,43.78 96,43.78 97.85,45.63 99.57,45.63 100.81,46.88 106.05,46.88 106.43,47.25 106.43,47.58 v1(106.73,47.88)
USB2_HOST3_DP: length 37.3
  TOP w0.114: J2.22 80.92,52.48 80.81,52.36 80.81,52.13 80.49,51.82 80.49,51.75 80.49,51.75 80.49,48.92 80.58,48.83 80.58,48.18 v1(80.83,47.93) ; R69.2 106.2,47.47 106.2,47.57 v1(105.89,47.88)
  BOTTOM w0.114: v1(80.83,47.93) 80.54,47.63 80.54,47.12 83.64,44.02 84.02,44.02 84.15,44.15 84.4,44.15 84.53,44.02 84.79,44.02 84.91,44.15 85.17,44.15 85.29,44.02 85.55,44.02 85.67,44.15 85.93,44.15 86.06,44.02 86.31,44.02 86.44,44.15 86.69,44.15 86.82,44.02 87.07,44.02 87.2,44.15 87.45,44.15 87.58,44.02 87.83,44.02 87.96,44.15 88.21,44.15 88.34,44.02 88.6,44.02 88.72,44.15 88.98,44.15 89.1,44.02 95.9,44.02 97.75,45.87 99.47,45.87 100.71,47.12 105.95,47.12 106.18,47.35 106.18,47.59 v1(105.89,47.88)
USB2_PWREN_H_GPIO4_C3: length 113.2
  TOP w0.127: v1(96.49,21.29) 96.49,21.64 96.11,22.02 96.11,25.91 95.83,26.19 95.83,26.97 93.29,29.51 93.29,31.06 93.55,31.32 93.55,36.93 v1(93.37,37.11) ; v1(104.98,10.49) 105.36,10.87 R70.1 ; J2.138 51.92,52.39 52.27,52.04 52.27,50.64 51.16,49.52 51.16,46.47 51.05,46.36 51.05,43.68 51.59,43.14 51.59,40.94 50.04,39.39 50.04,38.89 50.28,38.64 v1(50.28,38.56)
  BOTTOM w0.127: v1(96.49,21.29) 97.38,20.4 99.14,20.4 100.53,19 100.53,10.11 101.68,8.97 102.31,8.97 103.33,9.98 104.47,9.98 v1(104.98,10.49) ; v1(93.37,37.11) 92.56,37.92 78.69,37.92 67.89,27.13 51.13,27.13 50.24,28.02 50.24,37.16 49.74,37.66 49.74,38.02 v1(50.28,38.56)
USB3_HOST1_DM: length 61.2
  TOP w0.114: v1(43.73,59.19) 43.73,59.19 43.46,59.46 42.56,59.46 42.3,59.72 42.3,60.54 42.17,60.67 J2.169 ; R46.1 84.09,69.32 L7.2 84.09,68.78 83.81,68.49 83.81,68.24 83.56,67.98 82.67,67.98 82.41,68.24 82.41,71.09 82.8,71.49 82.8,73.58 v1(82.58,73.8)
  BOTTOM w0.114: v1(43.73,59.19) 43.73,59.2 44.02,59.49 44.25,59.49 44.5,59.74 44.5,60.48 46.33,62.31 47.83,62.31 49.24,63.72 49.87,63.72 55.33,69.18 60.93,69.18 66.93,75.18 66.93,75.85 67.37,76.29 67.87,76.29 68.69,77.11 76.8,77.11 79.22,74.69 82.37,74.69 82.82,74.25 82.82,74.03 v1(82.58,73.8)
USB3_HOST1_DM_: length 8.7
  TOP w0.114: L7.3 84.09,70.75 83.82,71.02 83.82,71.25 84,71.43 84,71.81 84.13,71.94 D14.2 D14.9 84.13,73.32 84.02,73.43 84.02,73.86 85.52,75.36 85.52,75.92 86.87,77.27 J6.11
USB3_HOST1_DP: length 60.9
  TOP w0.114: R47.1 83.29,69.32 L7.1 83.29,68.78 83.57,68.5 83.57,68.34 83.46,68.22 82.77,68.22 82.65,68.34 82.65,70.99 83.05,71.39 83.05,73.55 v1(83.29,73.8) ; J2.167 42.67,60.66 42.54,60.53 42.54,59.82 42.66,59.7 43.41,59.7 v1(43.73,60.02)
  BOTTOM w0.114: v1(83.29,73.8) 83.06,74.03 83.06,74.35 82.47,74.93 79.32,74.93 76.9,77.36 76.63,77.36 76.44,77.55 76.17,77.55 75.98,77.36 75.72,77.36 75.53,77.55 75.26,77.55 75.07,77.36 74.8,77.36 74.61,77.55 74.35,77.55 74.16,77.36 68.59,77.36 67.77,76.53 67.27,76.53 66.69,75.95 66.69,75.28 65.48,74.07 60.83,69.42 55.23,69.42 49.77,63.96 49.14,63.96 47.73,62.55 46.23,62.55 44.26,60.58 44.26,59.84 44.15,59.73 44.03,59.73 v1(43.73,60.02)
USB3_HOST1_DP_: length 9
  TOP w0.114: L7.4 83.29,70.72 83.58,71.01 83.58,71.35 83.76,71.53 83.76,71.81 83.63,71.94 D14.1 D14.10 83.63,73.3 83.78,73.44 83.78,73.96 85.28,75.46 85.28,76.02 86.32,77.06 86.32,77.29 86.2,77.4 85.57,77.4 J6.12
USB3_HOST1_PWREN_H_GPIO3_A0: length 35.9
  TOP w0.127: J2.71 68.67,63.18 v1(68.69,63.19) ; U6.4 95.51,65.29 96.09,64.72 96.09,63.32 96.19,63.22 v1(96.19,62.89)
  BOTTOM w0.127: v1(68.69,63.19) 68.68,63.19 68.68,63.37 69.27,63.96 69.67,63.96 71.22,65.51 79.71,65.51 80.45,64.76 82.16,64.76 83.21,63.7 83.21,62.84 83.85,62.2 95.07,62.2 95.76,62.89 v1(96.19,62.89)
USB3_HOST1_SSRXN: length 63.4
  TOP w0.114: v1(46.35,59.49) 46.57,59.27 46.57,58.72 45.56,57.71 42.47,57.71 40.54,59.63 40.54,60.27 40.67,60.4 J2.175 ; R423.1 87.5,68.44 87.5,68.61 86.94,69.16 R375.1 87.14,69.55 87.3,69.55 v2(87.58,69.82)
  BOTTOM w0.114: v2(87.58,69.82) 87.41,69.66 87.11,69.66 86.59,70.18 86.59,71 85.38,72.21 82.45,72.21 81.65,73.01 79.11,73.01 77.3,74.82 74.22,74.82 73.88,74.47 68.04,74.47 61.46,67.89 58.66,67.89 58.03,67.26 57.73,67.26 57.61,67.39 57.35,67.39 57.23,67.26 56.97,67.26 56.85,67.39 56.59,67.39 56.46,67.26 56.21,67.26 56.08,67.39 55.83,67.39 55.7,67.26 55.32,67.26 50.55,62.48 49.8,62.48 48.34,61.02 47.22,61.02 46.57,60.37 46.57,59.71 v1(46.35,59.49)
USB3_HOST1_SSRXN_: length 12.4
  TOP w0.114: v2(87.57,74.19) 87.83,73.93 87.83,73.7 87.7,73.57 D17.10 D17.1 87.7,71.92 87.83,71.79 87.83,71.6 87.46,71.23 87.46,70.98 87.1,70.61 87.1,70.4 R375.2
  BOTTOM w0.114: J6.14 83.2,75.77 83.32,75.65 83.32,75.35 83.9,74.76 83.9,74.02 84.44,73.48 86.23,73.48 87.39,74.64 87.71,74.64 87.83,74.52 87.83,74.45 v2(87.57,74.19)
USB3_HOST1_SSRXP: length 63.4
  TOP w0.114: v2(87.6,69.24) 87.78,69.42 88.12,69.42 R376.1 88.21,69.09 87.75,68.62 87.75,68.43 R422.1 ; J2.177 40.17,60.4 40.3,60.27 40.3,59.53 42.37,57.47 45.66,57.47 46.81,58.62 46.81,59.27 v1(47.03,59.49)
  BOTTOM w0.114: v1(47.03,59.49) 46.81,59.71 46.81,60.27 47.32,60.78 48.44,60.78 49.9,62.24 50.65,62.24 55.42,67.02 58.13,67.02 58.76,67.65 61.56,67.65 68.14,74.23 73.98,74.23 74.32,74.57 77.2,74.57 79.01,72.77 81.55,72.77 82.35,71.97 85.28,71.97 86.35,70.9 86.35,70.08 87.01,69.42 87.43,69.42 v2(87.6,69.24)
USB3_HOST1_SSRXP_: length 12.5
  TOP w0.114: v2(88.33,74.19) 88.07,73.93 88.07,73.7 88.2,73.57 D17.9 D17.2 88.2,71.92 88.07,71.79 88.07,71.5 87.7,71.13 87.7,70.97 88.06,70.61 88.06,70.38 R376.2
  BOTTOM w0.114: J6.15 83.67,75.77 83.56,75.65 83.56,75.45 84.14,74.86 84.14,74.12 84.54,73.72 86.13,73.72 87.29,74.88 87.81,74.88 88.07,74.62 88.07,74.45 v2(88.33,74.19)
USB3_HOST1_SSTXN: length 64.6
  TOP w0.114: v2(89.74,69.8) 89.71,69.8 89.56,69.65 89.45,69.65 C290.1 89.1,69.24 89.57,68.77 89.57,68.67 89.52,68.61 89.52,68.4 C187.1 ; v1(44.97,59.49) 45.19,59.27 45.19,58.65 44.98,58.45 42.8,58.45 41.54,59.7 41.54,60.27 41.67,60.4 J2.171
  BOTTOM w0.114: v2(89.74,69.8) 89.56,69.62 89.29,69.62 85.95,72.96 82.77,72.96 81.98,73.75 79.46,73.75 76.61,76.61 69.11,76.61 61.16,68.66 55.63,68.66 50.19,63.22 49.47,63.22 48.03,61.79 46.61,61.79 45.17,60.35 45.17,59.69 v1(44.97,59.49)
USB3_HOST1_SSTXN_: length 6.4
  TOP w0.114: J6.17 89.32,74.88 89.32,73.42 89.2,73.3 D17.7 D17.4 89.2,71.92 89.33,71.79 89.33,71.47 89.6,71.2 89.6,70.88 89.26,70.54 89.26,70.35 C290.2
USB3_HOST1_SSTXP: length 65
  TOP w0.114: v1(45.65,59.49) 45.43,59.27 45.43,58.55 45.08,58.2 42.7,58.2 41.3,59.6 41.3,60.27 41.17,60.4 J2.173 ; C189.1 89.76,68.4 89.76,68.51 89.81,68.57 89.81,68.71 90.37,69.27 C291.1 90.29,69.38 89.93,69.38 v2(89.76,69.22)
  BOTTOM w0.114: v2(89.76,69.22) 89.66,69.32 89.6,69.38 89.19,69.38 85.85,72.72 82.67,72.72 81.88,73.51 79.36,73.51 76.51,76.37 69.21,76.37 61.26,68.41 55.73,68.41 50.29,62.98 49.57,62.98 48.13,61.54 46.71,61.54 45.42,60.25 45.42,59.72 v1(45.65,59.49)
USB3_HOST1_SSTXP_: length 6.4
  TOP w0.114: J6.18 89.56,74.89 89.56,73.43 89.7,73.3 D17.6 D17.5 89.7,71.94 89.57,71.81 89.57,71.57 89.84,71.3 89.84,70.89 90.2,70.54 90.2,70.38 C291.2
USB3_OTG0_DM: length 107.2
  TOP w0.114: R29.1 124.41,77.44 L5.2 124.3,77.18 124.02,76.91 124.02,76.84 v1(124.28,76.58) ; J2.189 37.17,60.4 37.3,60.27 37.3,59.16 41.2,55.26 47.47,55.26 50.98,58.76 50.98,59.33 v1(51.2,59.55)
  BOTTOM w0.114: v1(51.2,59.55) 51,59.74 51,59.9 51.12,60.02 51.64,60.02 55.7,64.08 61.15,64.08 69.06,72 75.43,72 76,71.42 76,71.13 76.82,70.31 84.33,70.31 86.09,68.54 92.34,68.54 94.46,70.66 100.63,70.66 101.83,69.47 103.82,69.47 104.84,70.49 104.84,72.22 106.62,74 113.71,74 115.61,75.9 123.8,75.9 124.07,76.16 124.07,76.37 v1(124.28,76.58)
USB3_OTG0_DM_: length 14.5
  TOP w0.114: R29.2 124.3,78.74 L5.3 124.3,79.18 124.02,79.46 124.02,79.6 124.14,79.72 126.53,79.72 127.43,80.62 127.43,80.98 127.44,80.99 127.44,81.57 D12.2 127.81,82.25 127.58,82.25 127.44,82.38 127.44,82.64 v1(127.69,82.88) 127.58,82.98 127.58,83.36 127.72,83.49 J5.A7 ; v1(128.39,85.68) 128.08,85.37 128.08,85.3 128.59,84.8 128.59,84.59 128.72,84.47 J5.B7
  BOTTOM w0.114: v1(127.69,82.88) 127.46,83.1 127.46,83.9 128.09,84.53 128.09,85.38 v1(128.39,85.68)
USB3_OTG0_DP: length 107.1
  TOP w0.114: v1(50.52,59.55) 50.74,59.33 50.74,58.86 47.37,55.5 41.3,55.5 37.54,59.26 37.54,60.27 37.67,60.4 J2.187 ; R34.1 123.39,77.44 L5.1 123.5,77.18 123.78,76.9 123.78,76.79 v1(123.57,76.58)
  BOTTOM w0.114: v1(123.57,76.58) 123.83,76.33 123.83,76.26 123.7,76.14 115.51,76.14 113.61,74.24 112.6,74.24 112.47,74.37 112.22,74.37 112.09,74.24 111.84,74.24 111.71,74.37 111.46,74.37 111.33,74.24 111.07,74.24 110.95,74.37 110.69,74.37 110.57,74.24 110.31,74.24 110.19,74.37 109.93,74.37 109.8,74.24 109.55,74.24 109.42,74.37 109.17,74.37 109.04,74.24 108.79,74.24 108.66,74.37 108.41,74.37 108.28,74.24 108.03,74.24 107.9,74.37 107.65,74.37 107.52,74.24 106.52,74.24 104.6,72.32 104.6,70.59 103.72,69.71 101.93,69.71 100.73,70.9 94.36,70.9 92.24,68.78 86.19,68.78 84.43,70.55 76.92,70.55 76.24,71.23 76.24,71.52 75.53,72.24 68.96,72.24 61.05,64.33 55.6,64.33 51.54,60.26 51.02,60.26 50.76,60 50.76,59.79 v1(50.52,59.55)
USB3_OTG0_DP_: length 14.5
  TOP w0.114: J5.B6 127.22,83.43 127.3,83.34 127.3,83.19 v1(127,82.88) 127.2,82.68 127.2,82.37 127.08,82.25 126.85,82.25 D10.2 127.2,81.58 127.2,81.09 127.19,81.08 127.19,80.72 126.43,79.96 124.04,79.96 123.78,79.7 123.78,79.46 123.5,79.18 L5.4 123.5,78.74 R34.2 ; J5.A6 128.22,84.48 128.35,84.61 128.35,84.7 127.84,85.2 127.84,85.39 v1(127.55,85.68)
  BOTTOM w0.114: v1(127,82.88) 127.22,83.1 127.22,84 127.85,84.63 127.85,85.38 v1(127.55,85.68)
USB3_OTG0_ID: length 133.3
  TOP w0.127: v1(113.84,79.93) 113.49,79.58 113.49,74.8 113.89,74.4 114.25,74.4 115.65,73 115.65,68.12 115.19,67.67 115.19,66.88 115.65,66.42 115.65,65.3 v1(115.54,65.2) ; v1(52.9,73.37) 53.01,73.25 53.16,73.25 53.54,72.87 53.54,68.78 50.5,65.74 42.56,65.74 40.3,63.47 36.55,63.47 36.27,63.2 36.27,62.66 36.17,62.56 J2.193 ; v1(115.49,50.19) 115.19,50.19 113.23,52.15 113.23,56.72 111.4,58.55 111.4,60.6 114.38,63.58 v1(115.77,63.58)
  BOTTOM w0.127: v1(115.54,65.2) 115.11,64.77 115.11,64.24 v1(115.77,63.58) ; v1(52.9,73.37) 52.86,73.41 52.86,73.71 52.67,73.9 52.67,74.28 53.44,75.05 53.44,76.73 55.73,79.02 56.63,79.02 56.93,79.32 57.57,79.96 58.93,79.96 58.93,79.96 68.66,79.96 69.67,78.94 71.24,78.94 72.34,80.04 80.16,80.04 82.63,82.5 90.25,82.5 92.53,80.21 113.21,80.21 113.49,79.93 v1(113.84,79.93) ; Q1.3 115.39,50.09 v1(115.49,50.19) R31.2
USB3_OTG0_SSRXN: length 56.3
  TOP w0.114: v2(77.9,71.6) 77.72,71.42 77.72,70.15 77.58,70.02 77.58,68.71 77.7,68.59 78.44,68.59 78.55,68.71 78.55,68.98 R48.1 ; v1(49.14,59.49) 49.34,59.3 49.34,58.74 46.84,56.24 41.71,56.24 38.54,59.4 38.54,60.27 38.67,60.4 J2.183
  BOTTOM w0.114: v2(77.9,71.6) 77.73,71.78 77.73,72.27 77.02,72.97 68.65,72.97 60.77,65.1 55.3,65.1 51.21,61.01 50.46,61.01 49.39,59.95 49.39,59.74 v1(49.14,59.49)
USB3_OTG0_SSRXN_: length 16.6
  TOP w0.114: J6.5 82.44,79.01 82.91,79.48 83.23,79.48 83.32,79.4 83.32,78.7 83.06,78.44 82.99,78.4 82.63,78.23 82.56,78.19 81.93,78.19 81.37,78.75 78.46,78.75 77.89,78.18 77.89,75.19 78.76,74.32 78.76,73.44 78.63,73.31 D107.10 D107.1 78.63,71.67 78.76,71.54 78.76,71.12 78.55,70.92 78.55,70.57 R48.2
USB3_OTG0_SSRXP: length 57
  TOP w0.114: v2(77.32,71.6) 77.48,71.44 77.48,70.25 77.34,70.12 77.34,68.61 77.6,68.35 78.54,68.35 78.79,68.61 78.79,68.97 R49.1 ; v1(49.83,59.49) 49.58,59.25 49.58,58.64 46.94,55.99 41.61,55.99 38.3,59.3 38.3,60.27 38.17,60.4 J2.185
  BOTTOM w0.114: v1(49.83,59.49) 49.64,59.68 49.64,59.85 50.56,60.77 51.31,60.77 55.4,64.86 60.87,64.86 68.75,72.73 76.92,72.73 77.48,72.17 77.48,71.77 v2(77.32,71.6)
USB3_OTG0_SSRXP_: length 15.8
  TOP w0.114: R49.2 78.79,70.58 78.79,70.82 79,71.02 79,71.54 79.13,71.67 D107.2 D107.9 79.13,73.32 79,73.45 79,74.42 78.13,75.29 78.13,78.08 78.56,78.51 81.27,78.51 81.83,77.95 82.62,77.95 82.73,78.02 83.11,78.19 83.21,78.26 83.56,78.6 83.56,78.85 83.67,78.97 J6.6
USB3_OTG0_SSTXN: length 59.6
  TOP w0.114: J2.179 39.67,60.4 39.54,60.27 39.54,59.54 42.11,56.97 46.14,56.97 47.98,58.81 47.98,59.23 v1(47.73,59.48) ; C39.1 80.45,68.96 80.45,68.52 80.67,68.3 81.55,68.3 81.8,68.56 81.8,70.87 81.81,70.88 81.81,70.88 v2(81.97,71.04)
  BOTTOM w0.114: v2(81.97,71.04) 81.79,71.23 81.79,71.53 81.08,72.24 78.82,72.24 77.32,73.74 68.34,73.74 60.45,65.85 54.97,65.85 51.29,62.18 50.87,61.75 50.13,61.75 48.66,60.27 48.34,60.27 47.97,59.91 47.97,59.71 v1(47.73,59.48)
USB3_OTG0_SSTXN_: length 17.5
  TOP w0.114: J6.8 89.13,78.97 89.24,78.85 89.24,78.38 88.98,78.12 88.07,78.12 87.86,78.33 86.96,78.33 86.78,78.16 86.12,78.16 85.96,78.31 84.93,78.31 83.96,77.34 83.96,76.99 83.32,76.35 83.32,75.46 82.81,74.94 80.78,74.94 80.26,74.42 80.26,73.45 80.13,73.32 D107.7 D107.4 80.13,71.92 80.26,71.79 80.26,71.01 80.43,70.84 80.43,70.57 C39.2
USB3_OTG0_SSTXP: length 58.8
  TOP w0.114: v1(48.44,59.48) 48.22,59.26 48.22,58.71 46.24,56.73 42.01,56.73 39.3,59.44 39.3,60.27 39.17,60.4 J2.181 ; C41.1 80.69,68.96 80.69,68.62 80.77,68.54 81.45,68.54 81.56,68.66 81.56,70.87 v2(81.39,71.04)
  BOTTOM w0.114: v1(48.44,59.48) 48.21,59.71 48.21,59.81 48.44,60.03 48.76,60.03 50.23,61.51 50.97,61.51 51.53,62.08 55.07,65.61 60.55,65.61 68.44,73.49 77.22,73.49 78.72,72 80.98,72 81.55,71.43 81.55,71.2 v2(81.39,71.04)
USB3_OTG0_SSTXP_: length 18.3
  TOP w0.114: C41.2 80.67,70.6 80.67,70.94 80.5,71.11 80.5,71.76 80.63,71.89 D107.5 D107.6 80.63,73.32 80.5,73.45 80.5,74.32 80.88,74.7 82.91,74.7 83.57,75.36 83.57,76.25 84.2,76.89 84.2,77.24 85.03,78.07 85.86,78.07 86.02,77.91 86.88,77.91 87.06,78.09 87.76,78.09 87.97,77.88 89.08,77.88 89.49,78.28 89.49,79.2 89.7,79.41 90.16,79.41 90.44,79.13 J6.9
USB3_OTG0_VBUSDET: length 104.9
  TOP w0.127: R28.2 R27.2 122.77,81.11 v1(122.24,80.58) ; J2.191 36.67,62.54 36.55,62.66 36.55,63.08 36.68,63.21 40.48,63.21 42.72,65.46 50.58,65.46 53.8,68.68 53.8,73.43 v1(53.14,74.09)
  BOTTOM w0.127: v1(53.14,74.09) 53.14,74.39 53.7,74.95 53.7,76.62 55.84,78.77 56.74,78.77 57.19,79.21 57.68,79.71 68.53,79.71 69.55,78.69 71.35,78.69 72.44,79.78 80.29,79.78 82.75,82.25 90.12,82.25 92.41,79.96 112.47,79.96 112.98,79.45 118.82,79.45 120.22,80.85 121.97,80.85 v1(122.24,80.58)
USB3_PWREN_H_GPIO4_C4: length 96.2
  TOP w0.127: v1(93.57,37.82) 93.85,37.54 93.85,31.24 93.55,30.94 93.55,29.64 95.96,27.23 95.96,27.21 96.09,27.08 96.09,26.29 96.37,26.01 96.37,22.15 96.98,21.54 96.98,19.35 R77.1 ; J2.140 51.42,52.46 52.02,51.87 52.02,50.75 50.9,49.63 50.9,46.58 50.79,46.47 50.79,43.57 51.33,43.03 51.33,41.05 49.76,39.47 49.76,38.4 50.28,37.88 v1(50.28,37.8)
  BOTTOM w0.127: v1(50.28,37.8) 50.37,37.8 50.5,37.67 50.5,28.14 51.26,27.38 67.77,27.38 78.56,38.18 93.22,38.18 v1(93.57,37.82)
USB_OTG_PWREN_H_GPIO0_A5: length 147.9
  TOP w0.127: v1(123.29,47.35) 124.43,47.35 124.56,47.47 124.56,48.87 124.89,49.2 v1(125.02,49.2) ; v1(40.21,45.8) 39.7,45.8 38.56,46.94 36.86,46.94 35.18,48.62 33.83,48.62 33.35,49.1 31.95,49.1 31.42,49.63 J2.212
  BOTTOM w0.127: R32.1 123.33,47.57 123.33,47.39 v1(123.29,47.35) ; v1(40.21,45.8) 40.72,45.29 41.43,45.29 42,45.86 42.38,45.86 42.82,45.42 50.28,45.42 52.11,47.24 53.52,47.24 55.6,45.16 64.74,45.16 66.88,47.29 66.88,52.78 66.12,53.54 66.12,62.51 69.8,66.19 70.38,66.19 70.94,66.75 82.45,66.75 84.25,64.95 94.39,64.95 95.43,65.99 101.68,65.99 102.57,66.88 106.88,66.88 110.19,70.18 112.17,70.18 113.06,71.07 118.76,71.07 121.59,68.24 121.59,64.49 121.92,64.16 121.92,59.97 124.28,57.61 124.28,56.21 126.7,53.8 126.7,49.48 126.42,49.2 v1(125.02,49.2)
USIM_CLK: length 6.3
  BOTTOM w0.127: SIM1.C3 112.73,60.91 112.55,60.73 112.55,58.82 C185.1 113.38,58.44 D75.1 113.59,58.47 114.45,57.61 R335.2
USIM_CLK_: length 8.3
  TOP w0.127: v1(115.39,59.64) 115.11,59.36 115.11,58.37 114.78,58.04 114.78,54.58 115.3,54.07 J26.12
  BOTTOM w0.127: R335.1 115.39,59.4 v1(115.39,59.64)
USIM_DATA: length 35.6
  TOP w0.127: v1(112.85,83.16) 112.98,83.03 112.98,74.55 113.64,73.89 114,73.89 115.11,72.77 115.11,68.35 114.6,67.84 114.6,65.58 v1(114.38,65.35)
  BOTTOM w0.127: v1(114.38,65.35) 114.38,63.91 116.56,61.72 116.56,59.64 115.39,58.47 115.39,56.97 114.18,55.76 D73.1 114.07,55.55 R331.1 113.1,54.71 C188.1 R334.2 ; SIM1.C7 112.73,83.29 v1(112.85,83.16)
USIM_DATA_: length 2.2
  TOP w0.127: v1(115.98,54.58) 116.1,54.46 J26.10
  BOTTOM w0.127: v1(115.98,54.58) R334.1
USIM_RST: length 7.6
  BOTTOM w0.127: D72.1 109.53,58.47 109.5,58.44 109.48,58.44 109.46,58.41 C184.1 108.88,58.41 R332.2 ; D72.1 110.06,58.95 110.44,59.33 110.44,60.78 110.19,61.04 SIM1.C2 ; D72.1 110.27,58.47 R336.2
USIM_RST_: length 8.7
  TOP w0.127: v1(111.96,59.54) 111.96,58.75 113.49,57.23 113.49,55.07 114.5,54.06 J26.14
  BOTTOM w0.127: v1(111.96,59.54) 111.2,58.78 R336.1
USIM_VDD: length 22.8
  TOP w0.508: v1(108.17,59.35) 108.2,59.32 108.2,58.85 111.46,55.6 v1(111.46,55.55) 111.51,55.55 112.17,54.89 112.19,54.89 112.58,54.5 112.58,54.48 112.73,54.33 112.73,52.02 115.23,49.52 R333.2
  BOTTOM w0.508: 107.01,58.85 107.01,59.81 107.65,60.45 SIM1.C1 ; 107.01,58.85 D74.1 106.6,58.44 C186.1 C183.1 ; 107.01,58.85 107.42,59.26 108.08,59.26 ; v1(108.17,59.35) 108.08,59.26 ; 108.08,59.26 107.98,59.16 R332.1 ; v1(111.46,55.55) R331.2
VOLN: length 42.9
  TOP w0.203: v1(125.55,56.34) 125.88,56.01 C73.1 D30.2 127.61,56.08 128.98,56.08 129.49,56.59 129.49,58.27 132.16,60.93 J12.1 ; L11.2 109.49,71.13 109.17,71.45 108.79,71.45 v1(108.66,71.32)
  BOTTOM w0.203: v1(125.55,56.34) 125.76,56.54 125.76,57.38 124.87,58.27 124.54,58.27 122.61,60.2 122.61,68.17 119.08,71.7 112.75,71.7 111.94,70.89 110.24,70.89 109.55,71.58 108.92,71.58 v1(108.66,71.32)
VOLP: length 44.8
  TOP w0.203: J12.2 131.29,63.62 131.29,60.55 129.16,58.42 129.16,56.77 128.85,56.46 127.61,56.46 D31.2 C74.1 125.88,56.78 v1(126.31,56.34) ; v1(108.66,72.21) 108.9,71.97 109.19,71.97 109.49,72.27 L12.2
  BOTTOM w0.203: v1(126.31,56.34) 126.11,56.54 126.11,57.53 125.02,58.62 124.66,58.62 122.94,60.35 122.94,68.31 119.16,72.09 112.6,72.09 111.78,71.26 110.37,71.26 109.68,71.96 108.92,71.96 v1(108.66,72.21)
VORN: length 30.4
  TOP w0.203: v1(123.11,71.53) 123.11,71.53 122.77,71.53 L13.2 ; v1(125.48,58.9) 125.88,58.5 C76.1 D32.2 127.54,58.78 128.55,58.78 128.6,58.83 128.61,58.83 130.56,60.77 130.56,65.11 130.58,65.14 130.58,67.06 130.78,67.26 131.38,67.26 J12.3
  BOTTOM w0.203: v1(123.11,71.53) 123.22,71.64 123.54,71.64 123.95,71.22 123.95,69.55 123.27,68.87 123.27,64.34 123.95,63.66 123.95,63.65 123.95,61.06 125.65,59.36 125.65,59.08 v1(125.48,58.9)
VORP: length 31.2
  TOP w0.203: v1(126.19,58.93) 125.88,59.24 C77.1 D33.2 127.54,59.16 128.47,59.16 130.23,60.91 130.23,67.31 130.55,67.64 131.32,67.64 J12.4 ; v1(123.11,72.24) 122.8,72.24 L14.2
  BOTTOM w0.203: v1(126.19,58.93) 125.98,59.13 125.98,59.51 124.28,61.21 124.28,63.83 123.65,64.47 123.65,68.78 124.28,69.42 124.28,71.4 123.65,72.03 123.32,72.03 v1(123.11,72.24)
WIFI1T1R_CLK: length 56.3
  TOP w0.127: U18.17 106.76,25.35 106.67,25.43 106.67,25.9 106.83,26.06 106.83,28.6 105.76,29.67 96.39,29.67 95.61,30.45 95.61,30.66 95.22,31.05 95.22,31.51 95.3,31.59 95.3,44.17 v1(94.82,44.65)
  BOTTOM w0.127: v1(94.82,44.65) 94.75,44.65 94.24,45.16 85.4,45.16 81.47,49.1 81.47,56.86 80.6,57.73 C112.2 79.9,57.73 R187.2
